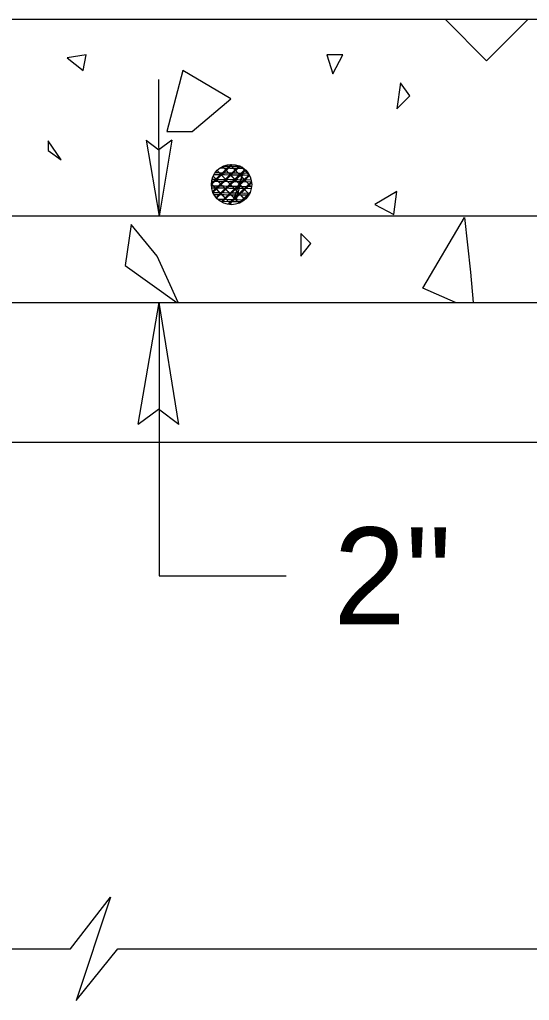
# Model space of a CAD drawing. Extents: x 26.41 to 33.74, y 20.66 to 30.6.
# Drawn here: x 32.669 to 32.985, y 27.226 to 27.834 of the extents above; entities that cross this region are included whole.
import ezdxf

# ---------------------------------------------------------------- set-up
doc = ezdxf.new("R2010")
doc.units = 0
for name, color, linetype in [('DETL-DIMS', 7, 'Continuous'), ('DETL-LINE', 7, 'Continuous'), ('DETL-NOTE', 7, 'Continuous'), ('DETL-PATT', 7, 'Continuous')]:
    doc.layers.add(name, color=color, linetype=linetype)

msp = doc.modelspace()

# ---------------------------------------------------------------- linework, layer by layer
at = {"layer": 'DETL-DIMS'}
for p, q in [((32.75538, 27.71188), (32.75507, 27.79662)), ((32.74737, 27.75901), (32.75538, 27.71188)), ((32.74737, 27.75901), (32.75523, 27.75315)), ((32.76309, 27.75909), (32.75523, 27.75315)), ((32.76309, 27.75909), (32.75538, 27.71188)), ((32.74241, 27.583), (32.75538, 27.65839)), ((32.76757, 27.58284), (32.75538, 27.65839)), ((32.75538, 27.65839), (32.75538, 27.48902)), ((32.74241, 27.583), (32.75503, 27.59235)), ((32.76757, 27.58284), (32.75503, 27.59235)), ((32.75538, 27.48902), (32.83399, 27.48902))]:
    msp.add_line(p, q, dxfattribs=at)
at = {"layer": 'DETL-LINE'}
for p, q in [((33.34406, 27.83377), (31.7863, 27.83377)), ((32.79933, 27.74341), (32.78982, 27.73425)), ((32.7998, 27.74313), (32.79025, 27.73397)), ((32.8022, 27.74046), (32.79268, 27.73126)), ((32.7954, 27.74183), (32.80455, 27.73232)), ((32.80805, 27.74038), (32.79854, 27.73114)), ((32.80121, 27.74171), (32.81041, 27.7322)), ((32.78946, 27.73613), (32.79862, 27.72658)), ((32.79925, 27.73759), (32.7897, 27.72839)), ((32.79968, 27.73727), (32.79017, 27.72812)), ((32.80404, 27.7344), (32.7908, 27.73464)), ((32.80408, 27.73735), (32.79084, 27.73759)), ((32.80412, 27.73853), (32.79088, 27.73877)), ((32.79241, 27.73896), (32.80161, 27.72945)), ((32.80212, 27.73464), (32.79257, 27.72544)), ((32.80255, 27.73433), (32.79304, 27.72513)), ((32.80267, 27.74014), (32.79312, 27.73098)), ((32.80817, 27.73433), (32.79492, 27.73456)), ((32.80821, 27.73727), (32.79496, 27.73751)), ((32.80825, 27.73845), (32.795, 27.73869)), ((32.79528, 27.73602), (32.80448, 27.72646)), ((32.80507, 27.73751), (32.79555, 27.72827)), ((32.80554, 27.73719), (32.79595, 27.728)), ((32.79823, 27.73885), (32.80742, 27.72933)), ((32.80794, 27.73452), (32.79842, 27.72532)), ((32.80849, 27.74006), (32.79893, 27.73087)), ((32.8123, 27.73425), (32.79905, 27.73448)), ((32.8011, 27.73594), (32.81029, 27.72635)), ((32.81092, 27.73739), (32.80137, 27.72819)), ((32.81132, 27.73708), (32.8018, 27.72788)), ((32.78934, 27.73028), (32.7985, 27.72076)), ((32.80393, 27.7291), (32.79068, 27.72933)), ((32.80397, 27.73028), (32.79072, 27.73051)), ((32.804, 27.73322), (32.79076, 27.73346)), ((32.79233, 27.73315), (32.80149, 27.72359)), ((32.80805, 27.72902), (32.79481, 27.72925)), ((32.80809, 27.7302), (32.79485, 27.73043)), ((32.80813, 27.73315), (32.79489, 27.73338)), ((32.79516, 27.7302), (32.80436, 27.72065)), ((32.80499, 27.73165), (32.79544, 27.72249)), ((32.80542, 27.73134), (32.79587, 27.72214)), ((32.79811, 27.73307), (32.80735, 27.72348)), ((32.80786, 27.72867), (32.79831, 27.71951)), ((32.80825, 27.72839), (32.79874, 27.71919)), ((32.80837, 27.73421), (32.79882, 27.72501)), ((32.81218, 27.72894), (32.79893, 27.72918)), ((32.81222, 27.73012), (32.79897, 27.73036)), ((32.81226, 27.73307), (32.79901, 27.7333)), ((32.8108, 27.73153), (32.80125, 27.72238)), ((32.81124, 27.73122), (32.80169, 27.72206)), ((32.80385, 27.72497), (32.7906, 27.72521)), ((32.80389, 27.72615), (32.79064, 27.72639)), ((32.80794, 27.72194), (32.79469, 27.72218)), ((32.80797, 27.72489), (32.79473, 27.72513)), ((32.80801, 27.72607), (32.79477, 27.72631)), ((33.29328, 27.71188), (32.55162, 27.71188)), ((31.86633, 27.65839), (33.24596, 27.65839)), ((31.85811, 27.57172), (33.25865, 27.5718)), ((32.70039, 27.25786), (32.72528, 27.2899)), ((32.72528, 27.2899), (32.70381, 27.22583)), ((31.747, 27.25786), (32.70039, 27.25786)), ((32.70381, 27.22583), (32.72968, 27.25786)), ((32.72968, 27.25786), (33.38337, 27.25786))]:
    msp.add_line(p, q, dxfattribs=at)
for points in [[(32.79638, 27.74058), (32.78777, 27.73224)], [(32.79996, 27.74399), (32.7928, 27.73712)], [(32.80416, 27.74148), (32.79296, 27.74168)], [(32.80003, 27.74156), (32.79296, 27.74168)], [(32.79591, 27.74164), (32.79296, 27.74168)], [(32.80066, 27.74399), (32.79323, 27.7368)], [(32.79457, 27.7427), (32.80172, 27.73531)], [(32.80416, 27.74262), (32.79485, 27.74282)], [(32.80007, 27.7427), (32.79485, 27.74282)], [(32.79595, 27.74278), (32.79485, 27.74282)], [(32.80782, 27.7414), (32.79504, 27.74164)], [(32.80597, 27.74262), (32.79508, 27.74282)], [(32.80491, 27.74309), (32.79567, 27.73413)], [(32.79996, 27.74399), (32.79579, 27.73999)], [(32.80546, 27.74285), (32.79606, 27.73385)], [(32.80066, 27.74399), (32.79618, 27.73967)], [(32.80491, 27.74309), (32.79866, 27.737)], [(32.80546, 27.74285), (32.79905, 27.73668)], [(32.79909, 27.74396), (32.80467, 27.73814)], [(32.79909, 27.74396), (32.80754, 27.73519)], [(32.80782, 27.7414), (32.79917, 27.74156)], [(32.80597, 27.74262), (32.79921, 27.74274)], [(32.80852, 27.74081), (32.80149, 27.73401)], [(32.80892, 27.7405), (32.80192, 27.73374)], [(32.80782, 27.7414), (32.8033, 27.74148)], [(32.80597, 27.74262), (32.80334, 27.74266)], [(32.80628, 27.74246), (32.80766, 27.74101)], [(32.80628, 27.74246), (32.81053, 27.73806)], [(32.80628, 27.74246), (32.81135, 27.73719)], [(32.80707, 27.74164), (32.81135, 27.73719)], [(32.79681, 27.74026), (32.78773, 27.73153)], [(32.79382, 27.73739), (32.78773, 27.73153)], [(32.79088, 27.73452), (32.78773, 27.73153)], [(32.79339, 27.73771), (32.78777, 27.73224)], [(32.79044, 27.73484), (32.78777, 27.73224)], [(32.79992, 27.73448), (32.78816, 27.73468)], [(32.79579, 27.73452), (32.78816, 27.73468)], [(32.79166, 27.7346), (32.78816, 27.73468)], [(32.79626, 27.73472), (32.78848, 27.72725)], [(32.79669, 27.7344), (32.78871, 27.72674)], [(32.78887, 27.73672), (32.79575, 27.72957)], [(32.79996, 27.73743), (32.78934, 27.73763)], [(32.79583, 27.73751), (32.78934, 27.73763)], [(32.7917, 27.73759), (32.78934, 27.73763)], [(32.8, 27.73857), (32.79005, 27.73877)], [(32.79587, 27.73865), (32.79005, 27.73877)], [(32.79174, 27.73873), (32.79005, 27.73877)], [(32.79123, 27.74018), (32.79874, 27.73244)], [(32.81132, 27.73719), (32.79909, 27.73743)], [(32.81061, 27.73837), (32.79913, 27.73861)], [(32.81238, 27.73425), (32.80318, 27.7344)], [(32.81132, 27.73719), (32.80322, 27.73735)], [(32.81061, 27.73837), (32.80326, 27.73853)], [(32.80408, 27.73877), (32.81253, 27.72996)], [(32.81112, 27.73755), (32.80436, 27.73106)], [(32.81135, 27.73712), (32.80479, 27.73075)], [(32.80695, 27.73582), (32.81253, 27.72996)], [(32.8099, 27.73865), (32.81135, 27.73719)], [(32.78773, 27.73193), (32.79276, 27.7267)], [(32.78773, 27.73193), (32.79563, 27.72371)], [(32.78789, 27.73165), (32.78773, 27.73153)], [(32.79984, 27.73036), (32.78777, 27.73055)], [(32.79571, 27.73043), (32.78777, 27.73055)], [(32.79158, 27.73047), (32.78777, 27.73055)], [(32.79988, 27.7333), (32.78793, 27.7335)], [(32.79575, 27.73338), (32.78793, 27.7335)], [(32.79162, 27.73346), (32.78793, 27.7335)], [(32.7998, 27.72918), (32.78793, 27.72937)], [(32.79567, 27.72925), (32.78793, 27.72937)], [(32.79154, 27.72933), (32.78793, 27.72937)], [(32.79327, 27.73189), (32.78848, 27.72725)], [(32.79033, 27.72902), (32.78848, 27.72725)], [(32.79375, 27.73153), (32.78871, 27.72674)], [(32.79076, 27.7287), (32.78871, 27.72674)], [(32.79913, 27.73177), (32.7906, 27.72356)], [(32.79614, 27.7289), (32.7906, 27.72356)], [(32.79956, 27.73146), (32.79095, 27.72316)], [(32.79658, 27.72863), (32.79095, 27.72316)], [(32.802, 27.72878), (32.79378, 27.72084)], [(32.80243, 27.72851), (32.79426, 27.72061)], [(32.80098, 27.73008), (32.80852, 27.72226)], [(32.81238, 27.72894), (32.80306, 27.7291)], [(32.81257, 27.73012), (32.8031, 27.73028)], [(32.81257, 27.73307), (32.80314, 27.73322)], [(32.80397, 27.73295), (32.81112, 27.72552)], [(32.81253, 27.73319), (32.80424, 27.72525)], [(32.81261, 27.73256), (32.80467, 27.72493)], [(32.80683, 27.72996), (32.81112, 27.72552)], [(32.81253, 27.73319), (32.80723, 27.72808)], [(32.81261, 27.73256), (32.80766, 27.7278)], [(32.80982, 27.73283), (32.81253, 27.72996)], [(32.79976, 27.72623), (32.78883, 27.72642)], [(32.79563, 27.72631), (32.78883, 27.72642)], [(32.79151, 27.72635), (32.78883, 27.72642)], [(32.79972, 27.72505), (32.78946, 27.72525)], [(32.79559, 27.72513), (32.78946, 27.72525)], [(32.79147, 27.72521), (32.78946, 27.72525)], [(32.7932, 27.72603), (32.7906, 27.72356)], [(32.79363, 27.72576), (32.79095, 27.72316)], [(32.80381, 27.72202), (32.7919, 27.72222)], [(32.79968, 27.7221), (32.7919, 27.72222)], [(32.79555, 27.72218), (32.7919, 27.72222)], [(32.79221, 27.72733), (32.80011, 27.71907)], [(32.79901, 27.72591), (32.79378, 27.72084)], [(32.79603, 27.72304), (32.79378, 27.72084)], [(32.79945, 27.72564), (32.79426, 27.72061)], [(32.7965, 27.72277), (32.79426, 27.72061)], [(32.79508, 27.72434), (32.80011, 27.71907)], [(32.79803, 27.72721), (32.80495, 27.72002)], [(32.80487, 27.7258), (32.79803, 27.71927)], [(32.80188, 27.72293), (32.79803, 27.71927)], [(32.8053, 27.72552), (32.79874, 27.71919)], [(32.80231, 27.72265), (32.79874, 27.71919)], [(32.80813, 27.72194), (32.79882, 27.7221)], [(32.81069, 27.72485), (32.79886, 27.72505)], [(32.81135, 27.72599), (32.79889, 27.72623)], [(32.8009, 27.72422), (32.80495, 27.72002)], [(32.81069, 27.72485), (32.80298, 27.72497)], [(32.81135, 27.72599), (32.80302, 27.72615)], [(32.80385, 27.72709), (32.80852, 27.72226)], [(32.81167, 27.72666), (32.80463, 27.7199)], [(32.81073, 27.72572), (32.80463, 27.7199)], [(32.80774, 27.72285), (32.80463, 27.7199)], [(32.811, 27.72529), (32.80605, 27.72053)], [(32.811, 27.72529), (32.80605, 27.72053)], [(32.80813, 27.72253), (32.80605, 27.72053)], [(32.80672, 27.72411), (32.80852, 27.72226)], [(32.81167, 27.72666), (32.80711, 27.72226)], [(32.811, 27.72529), (32.80754, 27.72194)], [(32.8097, 27.72698), (32.81112, 27.72552)], [(32.81167, 27.72666), (32.8101, 27.72513)], [(32.811, 27.72529), (32.81053, 27.72481)], [(32.80377, 27.72084), (32.79351, 27.72104)], [(32.79964, 27.72092), (32.79351, 27.72104)], [(32.79551, 27.721), (32.79351, 27.72104)], [(32.80648, 27.7208), (32.79465, 27.721)], [(32.79791, 27.72135), (32.80011, 27.71907)], [(32.79889, 27.7201), (32.79803, 27.71927)], [(32.79937, 27.71978), (32.79874, 27.71919)], [(32.80648, 27.7208), (32.79878, 27.72092)], [(32.80648, 27.7208), (32.8029, 27.72084)], [(32.80813, 27.72194), (32.80294, 27.72202)], [(32.80377, 27.72124), (32.80495, 27.72002)], [(32.80475, 27.71998), (32.80463, 27.7199)]]:
    msp.add_lwpolyline(points, dxfattribs=at)
msp.add_circle((32.8002, 27.73153), 0.01249, dxfattribs=at)
at = {"layer": 'DETL-PATT'}
for points in [[(32.98379, 27.83377), (32.95828, 27.80826), (32.93277, 27.83377)], [(32.9391, 27.65839), (32.91866, 27.66723), (32.9446, 27.7111), (32.94837, 27.67714), (32.94987, 27.65839)], [(32.76721, 27.65839), (32.75405, 27.68704), (32.73801, 27.70685), (32.73424, 27.68138), (32.76623, 27.65839)]]:
    msp.add_lwpolyline(points, dxfattribs=at)
for points in [[(32.69839, 27.81015), (32.7083, 27.80213), (32.71018, 27.81203)], [(32.85923, 27.81203), (32.863, 27.80024), (32.86913, 27.81203)], [(32.77574, 27.76439), (32.7998, 27.78468), (32.77008, 27.80213), (32.76018, 27.76439)], [(32.90498, 27.79458), (32.90262, 27.77854), (32.91064, 27.78656)], [(32.6866, 27.75873), (32.6866, 27.7526), (32.69462, 27.74694)], [(32.80169, 27.72289), (32.80357, 27.72289), (32.80735, 27.73892)], [(32.88894, 27.71911), (32.90074, 27.71298), (32.90262, 27.72713)], [(32.84319, 27.70119), (32.84319, 27.68704), (32.84932, 27.69506)]]:
    msp.add_lwpolyline(points, close=True, dxfattribs=at)

# ---------------------------------------------------------------- texts
at = {"layer": 'DETL-NOTE'}
msp.add_text('2"', height=0.05998, dxfattribs=at).set_placement((32.86347, 27.45903))

doc.saveas('drawing.dxf')
